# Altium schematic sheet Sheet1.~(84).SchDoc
size A
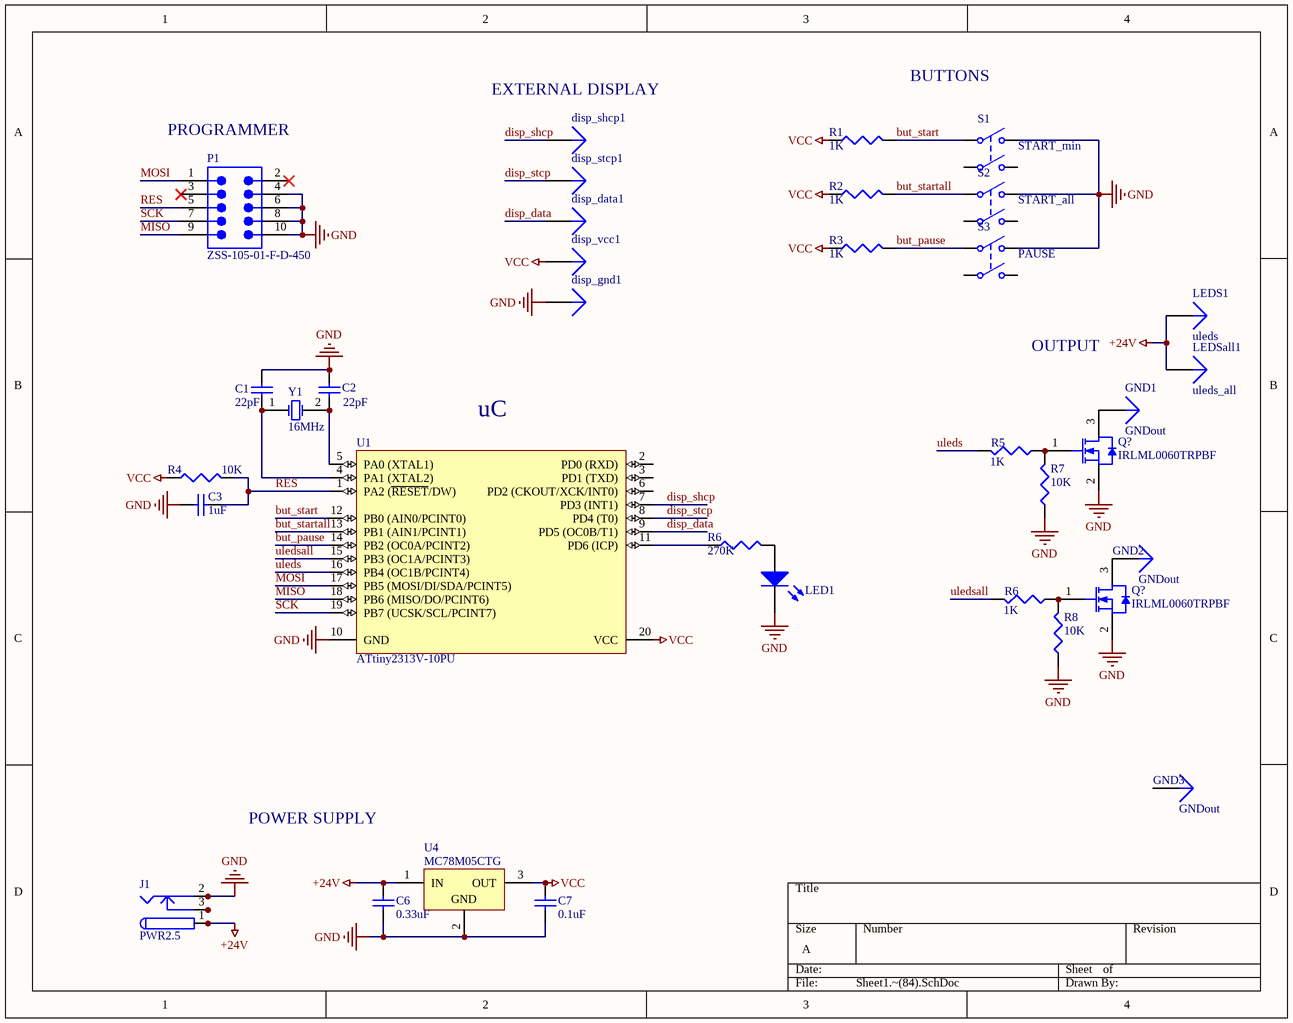
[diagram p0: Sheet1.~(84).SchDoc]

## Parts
(Parts that share a designator on the sheet are numbered #1, #2 ... from top to bottom, then left to right.)
C1  value 22pF  [CAPC1608L]  (hidden comment: Cap Semi)
C2  value 22pF  [CAPC1608L]  (hidden comment: Cap Semi)
C3  value 1uF  [CAPC1608L]  (hidden comment: Cap Semi)
C6  value 0.33uF  [CAPC1608L]  (hidden comment: Cap Semi)
C7  value 0.1uF  [CAPC1608L]  (hidden comment: Cap Semi)
disp_data1  uleds_all  [PIN1]  (value not drawn)
disp_gnd1  uleds_all  [PIN1]  (value not drawn)
disp_shcp1  uleds_all  [PIN1]  (value not drawn)
disp_stcp1  uleds_all  [PIN1]  (value not drawn)
disp_vcc1  uleds_all  [PIN1]  (value not drawn)
GND1  GNDout  [PIN1]
GND2  GNDout  [PIN1]
GND3  GNDout  [PIN1]
J1  PWR2.5  [PCBComponent_1]
LED1  151051YS04000  [Type 5mm]  (value not drawn)
LEDS1  uleds  [PIN1]
LEDSall1  uleds_all  [PIN1]
P1  ZSS-105-01-F-D-450  [SMTC-ZSS-105-01-X-D-450]
Q?#1  IRLML0060TRPBF  [NXP-SOT23_L]
Q?#2  IRLML0060TRPBF  [NXP-SOT23_L]
R1  value 1K  [CAPC1608L]  (hidden comment: Res3)
R2  value 1K  [CAPC1608L]  (hidden comment: Res3)
R3  value 1K  [CAPC1608L]  (hidden comment: Res3)
R4  value 10K  [CAPC1608L]  (hidden comment: Res3)
R5  value 1K  [CAPC1608L]  (hidden comment: Res3)
R6#1  value 270K  [CAPC1608L]  (hidden comment: Res3)
R6#2  value 1K  [CAPC1608L]  (hidden comment: Res3)
R7  value 10K  [CAPC1608L]  (hidden comment: Res3)
R8  value 10K  [CAPC1608L]  (hidden comment: Res3)
S1  START_min  [key]
S2  START_all  [key]
S3  PAUSE  [key]
U1  ATtiny2313V-10PU  [20P3]
U4  MC78M05CTG  [TO220]
Y1  16MHz  [PCBComponent_1 - duplicate]

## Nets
+24V: C6.2 J1.1 J1.1A J1.1B LEDS1.1 LEDSall1.1 U4.1(IN)
GND: C1.1 C2.1 C3.2 C6.1 C7.1 disp_gnd1.1 J1.2 J1.2A J1.2B LED1.1(K) P1.4 P1.6 P1.8 P1.10 Q?#1.2(S) Q?#2.2(S) R7.1 R8.1 S1.2(NO1) S2.2(NO1) S3.2(NO1) U1.10(GND) U4.2(GND)
VCC: C7.2 disp_vcc1.1 R1.1 R2.1 R3.1 R4.1 U1.20(VCC) U4.3(OUT)
but_pause: R3.2 S3.1(COMMON1) U1.14(PB2_(OC0A/PCINT2))
but_start: R1.2 S1.1(COMMON1) U1.12(PB0_(AIN0/PCINT0))
but_startall: R2.2 S2.1(COMMON1) U1.13(PB1_(AIN1/PCINT1))
disp_data: disp_data1.1 U1.9(PD5_(OC0B/T1))
disp_shcp: disp_shcp1.1 U1.7(PD3_(INT1))
disp_stcp: disp_stcp1.1 U1.8(PD4_(T0))
MISO: P1.9 U1.18(PB6_(MISO/DO/PCINT6))
MOSI: P1.1 U1.17(PB5_(MOSI/DI/SDA/PCINT5))
RES: C3.1 P1.5 R4.2 U1.1(PA2_(~{RESET}/DW))
SCK: P1.7 U1.19(PB7_(UCSK/SCL/PCINT7))
uleds: R5.2 U1.16(PB4_(OC1B/PCINT4))
uledsall: R6#2.2 U1.15(PB3_(OC1A/PCINT3))
NetC1_2: C1.2 U1.4(PA1_(XTAL2)) Y1.1(OSC1)
NetC2_2: C2.2 U1.5(PA0_(XTAL1)) Y1.2(OSC2)
NetGND1_1: GND1.1 Q?#1.3(D)
NetGND2_1: GND2.1 Q?#2.3(D)
NetJ1_3: J1.3 J1.3A J1.3B
NetLED1_2: LED1.2(A) R6#1.2
NetQ?#1_1: Q?#1.1(G) R5.1 R7.2
NetQ?#2_1: Q?#2.1(G) R6#2.1 R8.2
NetR6#1_1: R6#1.1 U1.11(PD6_(ICP))

Not connected (* = marked no-connect by the designer): GND3 1; P1 2* 3*; S1 3(COMMON2) 4(NO2); S2 3(COMMON2) 4(NO2); S3 3(COMMON2) 4(NO2); U1 2(PD0_(RXD)) 3(PD1_(TXD)) 6(PD2_(CKOUT/XCK/INT0))

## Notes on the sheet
- (near disp_shcp1) EXTERNAL DISPLAY
- BUTTONS
- (near P1) PROGRAMMER
- OUTPUT
- (near U1) uC
- POWER SUPPLY

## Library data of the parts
C1-C3 C6 C7 = Cap Semi: Capacitor (Semiconductor SIM Model)
disp_data1 disp_gnd1 disp_shcp1 disp_stcp1 disp_vcc1 GND1-GND3 LEDS1 LEDSall1 = Plug
J1 = PWR2.5: Low Voltage Power Supply Connector
LED1 = CMP-1488-00010-1: THT LED round mono-color color lens, WL-TMRW, Yellow; Manufacturer: Wuerth Elektronik
P1 = CMP-1024-00461-1: Manufacturer: Samtec; Pitch: 2.54 mm
Q?#1 Q?#2 = CMP-1259-00081-1: N-Channel Trench MOSFET, 60 V, 0.36 A, -55 to 150 degC, 3-Pin SOT23, Tape and Reel; PartNumber: 2N7002P,235; Manufacturer: NXP Semiconductors; ID [max] (A): 0.36; Channel Type: N; IDM [max] (A): 1.2; Automotive Qualified: Y; VGSth [typ] (V): 1.75; Packing: Tape & Reel; VDS [max] (V): 60
R1-R5 R6#1 R6#2 R7 R8 = Res3: Resistor
S1-S3 = SW-DPST: Double-Pole, Single-Throw Switch
U1 = CMP-0093-00017-1: Low Power tinyAVR® 8-Bit Microcontroller, 2K Flash Memory, 10MHz, Industrial Temperature, 20-Lead PDIP, Pb-Free
U4 = CMP-0244-00483-1: Positive Voltage Regulator, 5V, 3-Pin TO-220
Y1 = XTAL: Crystal Oscillator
